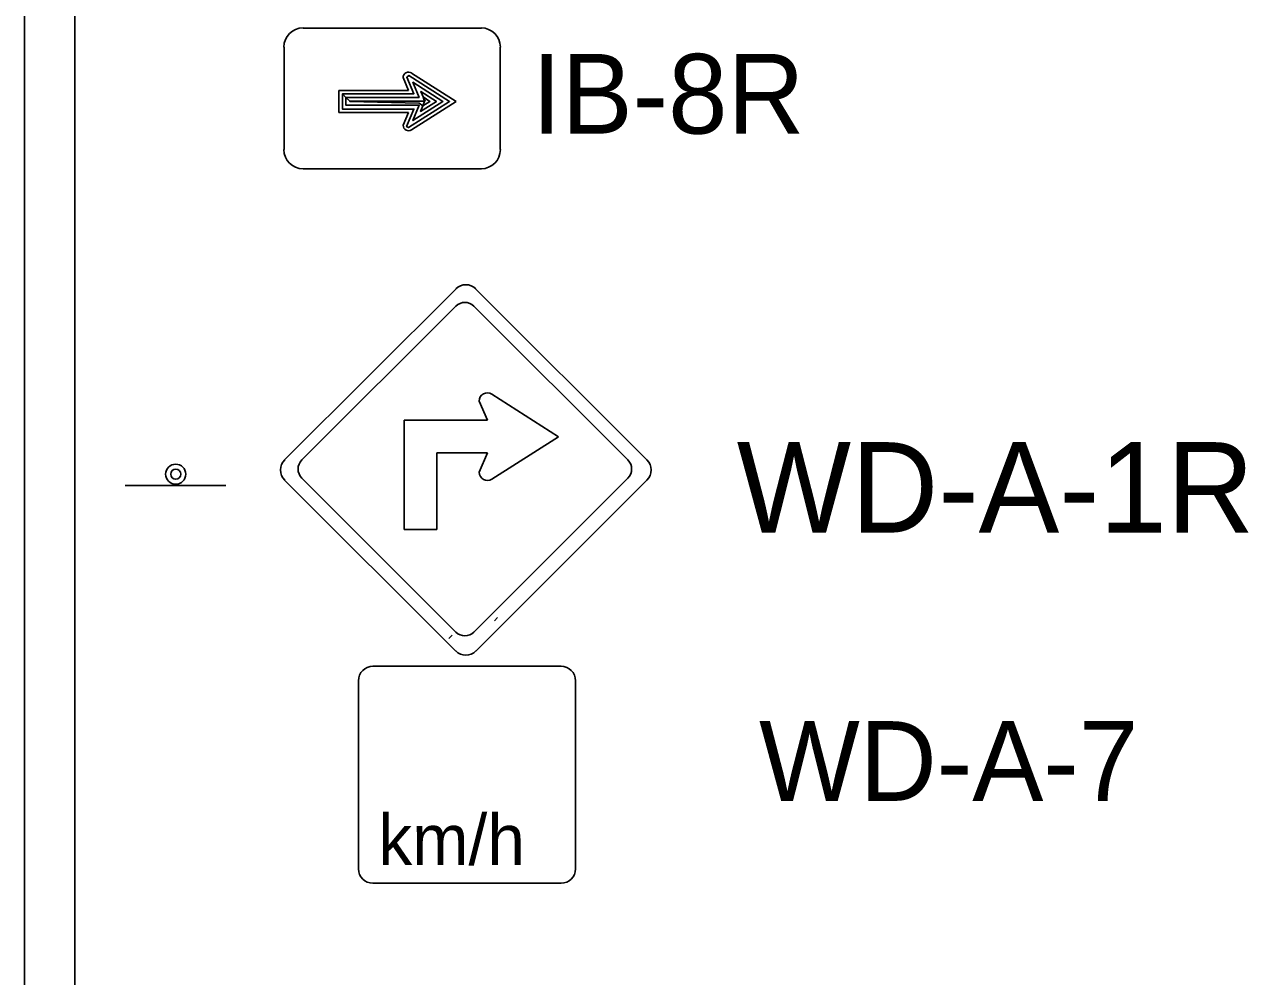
# Model space of a CAD drawing. Extents: x 1806 to 2022, y 110 to 389.
# Drawn here: x 1888.6 to 1918.07, y 170.8 to 193.73 of the extents above; entities that cross this region are included whole.
import ezdxf

# ---------------------------------------------------------------- set-up
doc = ezdxf.new("R2010")
doc.units = 0
for name, color, linetype in [('Level 10', 7, 'Continuous'), ('Level 2', 7, 'Continuous'), ('Level 44', 7, 'Continuous'), ('Level 50', 7, 'Continuous')]:
    doc.layers.add(name, color=color, linetype=linetype)

msp = doc.modelspace()

# ---------------------------------------------------------------- linework, layer by layer
at = {"layer": 'Level 10'}
for p, q in [((1888.603, 208.881), (1888.603, 146.057)), ((1889.812, 208.881), (1889.812, 146.057))]:
    msp.add_line(p, q, dxfattribs=at)
at = {"layer": 'Level 2'}
for p, q in [((1899.993, 179.444), (1899.915, 179.366)), ((1898.9, 179.019), (1898.822, 178.941))]:
    msp.add_line(p, q, dxfattribs=at)
at = {"layer": 'Level 44'}
for p, q in [((1895.311, 193.64), (1899.602, 193.64)), ((1894.855, 190.718), (1894.855, 193.183)), ((1900.054, 193.183), (1900.054, 190.718)), ((1897.849, 192.141), (1897.717, 192.449)), ((1897.922, 192.56), (1898.997, 191.877)), ((1896.172, 192.141), (1897.845, 192.141)), ((1896.172, 191.608), (1896.172, 192.141)), ((1898.997, 191.877), (1897.922, 191.19)), ((1897.849, 191.608), (1896.172, 191.608)), ((1897.721, 191.301), (1897.849, 191.608)), ((1899.602, 190.253), (1895.311, 190.253)), ((1898.987, 187.358), (1894.866, 183.244)), ((1903.587, 183.244), (1899.473, 187.358)), ((1895.279, 183.241), (1898.987, 186.944)), ((1899.425, 186.944), (1903.128, 183.241)), ((1899.852, 184.825), (1901.46, 183.8)), ((1899.748, 184.2), (1899.547, 184.658)), ((1897.743, 181.565), (1897.743, 184.2)), ((1897.743, 184.2), (1899.748, 184.2)), ((1901.46, 183.8), (1899.855, 182.778)), ((1899.751, 183.409), (1898.534, 183.409)), ((1898.534, 183.409), (1898.534, 181.565)), ((1899.553, 182.946), (1899.751, 183.409)), ((1894.866, 182.756), (1898.987, 178.638)), ((1894.87, 182.756), (1894.866, 182.756)), ((1898.987, 179.096), (1895.279, 182.801)), ((1903.128, 182.801), (1899.425, 179.096)), ((1899.473, 178.638), (1903.587, 182.756)), ((1891.03, 182.628), (1893.449, 182.628)), ((1898.534, 181.565), (1897.743, 181.565)), ((1896.992, 178.275), (1901.52, 178.275)), ((1896.642, 173.396), (1896.642, 177.926)), ((1901.87, 177.926), (1901.87, 173.396)), ((1896.642, 173.395), (1896.642, 173.396)), ((1901.52, 173.047), (1896.992, 173.047))]:
    msp.add_line(p, q, dxfattribs=at)
for points in [[(1896.262, 192.06), (1897.977, 192.06), (1897.807, 192.457), (1897.853, 192.5), (1898.839, 191.877), (1897.849, 191.245), (1897.802, 191.271), (1897.977, 191.693), (1896.258, 191.693), (1896.262, 192.06), (1896.343, 191.971), (1898.105, 191.971), (1897.956, 192.338), (1898.677, 191.877), (1897.956, 191.416), (1898.105, 191.783), (1896.343, 191.783), (1896.343, 191.971), (1896.433, 191.885), (1898.246, 191.885), (1898.148, 192.116), (1898.519, 191.877), (1898.139, 191.634), (1898.195, 191.77), (1898.365, 191.877), (1898.203, 191.984), (1898.237, 191.873), (1898.195, 191.77), (1898.109, 191.83), (1896.437, 191.873), (1896.433, 191.885)], [(1896.262, 192.06), (1897.977, 192.06)], [(1896.105, 190.249), (1896.177, 190.249)]]:
    msp.add_lwpolyline(points, dxfattribs=at)
for radius in [0.242, 0.121]:
    msp.add_circle((1892.244, 182.898), radius, dxfattribs=at)
for centre, radius, start, end in [((1895.311, 193.184), 0.462, 90, 180), ((1899.598, 193.184), 0.462, 0, 90), ((1897.851, 192.45), 0.132, 57.5038, 180.1058), ((1897.853, 191.302), 0.132, 180.1051, 302.4986), ((1895.311, 190.715), 0.462, 180, 270), ((1899.598, 190.715), 0.462, 270, 0), ((1899.229, 187.116), 0.345, 45, 135), ((1899.205, 186.725), 0.31, 45, 135), ((1899.746, 184.658), 0.198, 57.5038, 180.1058), ((1895.113, 183), 0.345, 135, 225), ((1895.5, 183.021), 0.31, 135, 225), ((1902.91, 183.021), 0.31, 315, 45), ((1903.346, 183), 0.345, 315, 45), ((1899.75, 182.945), 0.198, 180.1051, 302.4986), ((1899.205, 179.316), 0.31, 225, 315), ((1899.229, 178.884), 0.345, 225, 315), ((1896.992, 177.924), 0.349, 90, 180), ((1901.521, 177.924), 0.349, 360, 90), ((1896.992, 173.395), 0.349, 180, 270), ((1901.521, 173.395), 0.349, 270, 360)]:
    msp.add_arc(centre, radius, start, end, dxfattribs=at)

# ---------------------------------------------------------------- texts
at = {"layer": 'Level 10'}
msp.add_text('WD-A-1R', height=2.1774, rotation=360, dxfattribs=at).set_placement((1905.753, 181.492))
at = {"layer": 'Level 44'}
msp.add_text('km/h', height=1.218, dxfattribs=at).set_placement((1897.122, 173.489))
msp.add_text('km/h', height=1.218, dxfattribs=at).set_placement((1897.122, 173.489))
at = {"layer": 'Level 50'}
for s, height, p in [('IB-8R', 1.92, (1900.819, 191.1)), ('WD-A-7', 1.9199, (1906.289, 175.03))]:
    msp.add_text(s, height=height, rotation=360, dxfattribs=at).set_placement(p)

doc.saveas('drawing.dxf')
